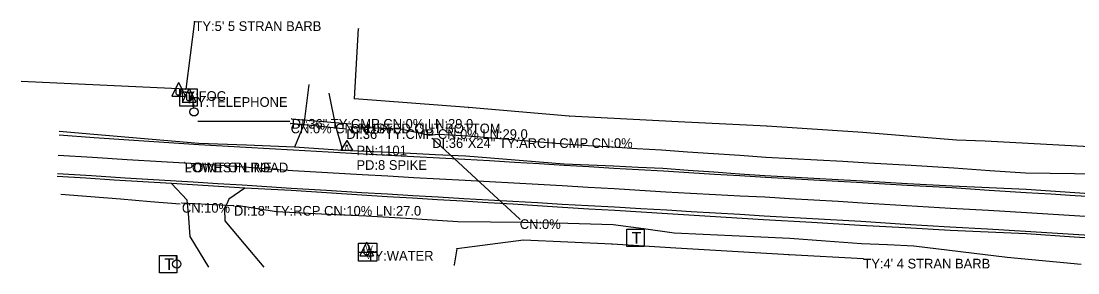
# Model space of a CAD drawing. Extents: x 592653 to 596268, y 1744647 to 1746025.
# Drawn here: x 592653 to 593199, y 1745895 to 1746025 of the extents above; entities that cross this region are included whole.
import ezdxf

# ---------------------------------------------------------------- set-up
doc = ezdxf.new("R2010")
doc.units = 0
for name, color, linetype in [('S_CROSS_DRAIN', 7, 'Continuous'), ('S_CROSS_DRAIN_ANNOT', 7, 'Continuous'), ('S_DITCHLINE', 7, 'Continuous'), ('S_DRG_PT_SYM', 7, 'Continuous'), ('S_DRIVEWAY', 7, 'Continuous'), ('S_EDGE_PAVEMENT', 7, 'Continuous'), ('S_ELECTRIC_UTILITIES_ANNOT', 7, 'Continuous'), ('S_FENCE', 7, 'Continuous'), ('S_FENCE_ANNOT', 7, 'Continuous'), ('S_MSC_PT_SYM', 7, 'Continuous'), ('S_PAVEMENT_CROWN', 7, 'Continuous'), ('S_SECONDARY_CTL', 7, 'Continuous'), ('S_SECONDARY_CTL_ANNOT', 7, 'Continuous'), ('S_SHOULDER', 7, 'Continuous'), ('S_SIDE_DRAIN', 7, 'Continuous'), ('S_SIDE_DRAIN_ANNOT', 7, 'Continuous'), ('S_SURVEY_TEXT_ANNOT', 7, 'Continuous'), ('S_TELEPHONE_UTILITIES', 7, 'Continuous'), ('S_UTILITY_POLE', 7, 'Continuous'), ('S_UTILITY_POLE_ANNOT', 7, 'Continuous'), ('S_UTL_PT_SYM', 7, 'Continuous'), ('S_WATER_UTILITIES', 7, 'Continuous')]:
    doc.layers.add(name, color=color, linetype=linetype)

msp = doc.modelspace()

# ---------------------------------------------------------------- linework, layer by layer
at = {"layer": 'S_CROSS_DRAIN'}
msp.add_line((592865.69, 1745964.34), (592910.93, 1745922.49), dxfattribs=at)
at = {"layer": 'S_DITCHLINE'}
for points in [[(592792.08, 1745973.03), (592768.3, 1745973.05), (592744.51, 1745973.07)], [(593210.37, 1745945.77), (593197.7, 1745945.94), (593185.04, 1745946.1), (593172.37, 1745946.27), (593153.81, 1745947.57), (593135.25, 1745948.88), (593113.22, 1745950.21), (593091.19, 1745951.54), (593077.92, 1745952.27), (593064.64, 1745953.01), (593051.37, 1745953.74), (593038.1, 1745954.47), (593024.61, 1745955.39), (593011.12, 1745956.3), (592997.63, 1745957.21), (592984.14, 1745958.12), (592971.51, 1745958.91), (592958.88, 1745959.69), (592946.25, 1745960.47), (592933.62, 1745961.25), (592908.96, 1745963.35), (592884.29, 1745965.44), (592868.82, 1745966.24), (592864.35, 1745965.72), (592849.46, 1745969.01), (592836.26, 1745969.62), (592823.06, 1745970.23)], [(592735.38, 1745930.29), (592719.99, 1745931.55), (592704.59, 1745932.82), (592689.2, 1745934.08), (592673.8, 1745935.34)], [(593201.1, 1745899.09), (593188.35, 1745900.29), (593175.59, 1745901.49), (593162.84, 1745902.69), (593138.7, 1745905.62), (593114.57, 1745908.55), (593101.03, 1745909.22), (593087.5, 1745909.89), (593068.98, 1745911.25), (593050.45, 1745912.61), (593035.52, 1745913.28), (593020.58, 1745913.94), (593005.65, 1745914.61), (592990.72, 1745915.27), (592974.93, 1745917.47), (592959.14, 1745919.68), (592935.83, 1745920.23), (592912.53, 1745920.78), (592895.73, 1745921.02), (592878.94, 1745921.25), (592855.23, 1745922.67), (592831.53, 1745924.08), (592808.39, 1745925.21), (592785.26, 1745926.35), (592764.59, 1745929.59)]]:
    msp.add_lwpolyline(points, dxfattribs=at)
at = {"layer": 'S_DRG_PT_SYM'}
for points in [[(592793.08, 1745974.32), (592793.08, 1745974.37), (592793.08, 1745974.32), (592793.03, 1745974.32), (592793.08, 1745974.32), (592793.08, 1745974.27), (592793.08, 1745974.32), (592793.13, 1745974.32)], [(592792.53, 1745971.92), (592792.53, 1745971.97), (592792.53, 1745971.92), (592792.48, 1745971.92), (592792.53, 1745971.92), (592792.53, 1745971.87), (592792.53, 1745971.92), (592792.58, 1745971.92)], [(592821.26, 1745969.02), (592821.26, 1745969.07), (592821.26, 1745969.02), (592821.21, 1745969.02), (592821.26, 1745969.02), (592821.26, 1745968.97), (592821.26, 1745969.02), (592821.31, 1745969.02)], [(592823.37, 1745971.73), (592823.37, 1745971.78), (592823.37, 1745971.73), (592823.32, 1745971.73), (592823.37, 1745971.73), (592823.37, 1745971.68), (592823.37, 1745971.73), (592823.42, 1745971.73)], [(592865.69, 1745964.34), (592865.69, 1745964.39), (592865.69, 1745964.34), (592865.64, 1745964.34), (592865.69, 1745964.34), (592865.69, 1745964.29), (592865.69, 1745964.34), (592865.74, 1745964.34)], [(592736.3, 1745930.89), (592736.3, 1745930.94), (592736.3, 1745930.89), (592736.25, 1745930.89), (592736.3, 1745930.89), (592736.3, 1745930.84), (592736.3, 1745930.89), (592736.35, 1745930.89)], [(592763.2, 1745929.37), (592763.2, 1745929.42), (592763.2, 1745929.37), (592763.15, 1745929.37), (592763.2, 1745929.37), (592763.2, 1745929.32), (592763.2, 1745929.37), (592763.25, 1745929.37)], [(592910.93, 1745922.49), (592910.93, 1745922.54), (592910.93, 1745922.49), (592910.88, 1745922.49), (592910.93, 1745922.49), (592910.93, 1745922.44), (592910.93, 1745922.49), (592910.98, 1745922.49)]]:
    msp.add_lwpolyline(points, dxfattribs=at)
at = {"layer": 'S_DRIVEWAY'}
for points in [[(592801.88, 1745992.08), (592799.24, 1745971.38), (592794.43, 1745959.79)], [(592819.54, 1745958.03), (592815.89, 1745970.58), (592812.43, 1745987.67)], [(592750.3, 1745897.83), (592740.6, 1745913.57), (592739.66, 1745925.53), (592739.05, 1745932.35), (592730.87, 1745940.97)], [(592768.88, 1745938.55), (592760.53, 1745932.96), (592758.35, 1745927.78), (592758.42, 1745921.74), (592768.54, 1745909.73), (592778.65, 1745897.71)]]:
    msp.add_lwpolyline(points, dxfattribs=at)
at = {"layer": 'S_EDGE_PAVEMENT'}
for points in [[(593210.51, 1745933.97), (593197.92, 1745934.69), (593185.33, 1745935.41), (593172.74, 1745936.14), (593153.5, 1745937.4), (593134.26, 1745938.67), (593111.16, 1745940.01), (593088.05, 1745941.35), (593075.52, 1745942.04), (593062.99, 1745942.73), (593050.46, 1745943.42), (593037.93, 1745944.11), (593024.74, 1745944.91), (593011.55, 1745945.71), (592998.37, 1745946.51), (592985.18, 1745947.31), (592972.35, 1745948.06), (592959.52, 1745948.81), (592946.68, 1745949.56), (592933.85, 1745950.31), (592921.01, 1745951.08), (592908.17, 1745951.85), (592895.33, 1745952.62), (592882.49, 1745953.38), (592869.38, 1745954.07), (592856.26, 1745954.75), (592843.15, 1745955.44), (592830.03, 1745956.12), (592811.89, 1745957.18), (592793.76, 1745958.24), (592769.41, 1745959.59), (592745.05, 1745960.93), (592727, 1745962.17), (592708.94, 1745963.41), (592690.89, 1745964.65), (592672.83, 1745965.89)], [(593221.91, 1745913.07), (593197.1, 1745914.61), (593172.28, 1745916.15), (593152.75, 1745917.3), (593133.21, 1745918.45), (593110.17, 1745919.85), (593087.13, 1745921.26), (593062.21, 1745922.72), (593037.29, 1745924.18), (593024.71, 1745924.93), (593012.14, 1745925.67), (592999.56, 1745926.41), (592986.99, 1745927.15), (592973.44, 1745927.92), (592959.89, 1745928.68), (592946.34, 1745929.45), (592932.79, 1745930.21), (592920.1, 1745930.92), (592907.41, 1745931.63), (592894.71, 1745932.34), (592882.02, 1745933.05), (592868.84, 1745933.84), (592855.67, 1745934.64), (592842.49, 1745935.44), (592829.31, 1745936.24), (592811.08, 1745937.35), (592792.86, 1745938.46), (592780.17, 1745939.27), (592767.48, 1745940.08), (592754.79, 1745940.89), (592742.1, 1745941.7), (592724.58, 1745942.76), (592707.05, 1745943.81), (592689.53, 1745944.87), (592672.01, 1745945.92)]]:
    msp.add_lwpolyline(points, dxfattribs=at)
at = {"layer": 'S_FENCE'}
for p, q in [((592742.82, 1746024.79), (592738.26, 1745989.68)), ((592825.51, 1745984.66), (592827.58, 1746020.99)), ((592738.26, 1745989.68), (592653.26, 1745993.68)), ((592884.37, 1745980.23), (592825.51, 1745984.66)), ((592936.51, 1745975.85), (592884.37, 1745980.23)), ((592992.8, 1745972.9), (592936.51, 1745975.85)), ((593038.69, 1745970.68), (592992.8, 1745972.9)), ((593088.26, 1745967.33), (593038.69, 1745970.68)), ((593136.69, 1745963.35), (593088.26, 1745967.33)), ((593151.46, 1745962.87), (593136.69, 1745963.35)), ((593223.26, 1745958.93), (593151.46, 1745962.87)), ((592878.42, 1745907.3), (592877.08, 1745898.91)), ((592912.83, 1745911.77), (592878.42, 1745907.3)), ((592958.65, 1745909.7), (592912.83, 1745911.77)), ((592991.58, 1745907.54), (592958.65, 1745909.7)), ((593050.1, 1745904.18), (592991.58, 1745907.54)), ((593088.53, 1745902.08), (593050.1, 1745904.18))]:
    msp.add_line(p, q, dxfattribs=at)
at = {"layer": 'S_MSC_PT_SYM'}
for points in [[(592742.82, 1746024.79), (592742.82, 1746024.84), (592742.82, 1746024.79), (592742.77, 1746024.79), (592742.82, 1746024.79), (592742.82, 1746024.74), (592742.82, 1746024.79), (592742.87, 1746024.79)], [(592827.58, 1746020.99), (592827.58, 1746021.04), (592827.58, 1746020.99), (592827.53, 1746020.99), (592827.58, 1746020.99), (592827.58, 1746020.94), (592827.58, 1746020.99), (592827.63, 1746020.99)], [(592653.26, 1745993.68), (592653.26, 1745993.73), (592653.26, 1745993.68), (592653.21, 1745993.68), (592653.26, 1745993.68), (592653.26, 1745993.63), (592653.26, 1745993.68), (592653.31, 1745993.68)], [(592738.26, 1745989.68), (592738.26, 1745989.73), (592738.26, 1745989.68), (592738.21, 1745989.68), (592738.26, 1745989.68), (592738.26, 1745989.63), (592738.26, 1745989.68), (592738.31, 1745989.68)], [(592825.51, 1745984.66), (592825.51, 1745984.71), (592825.51, 1745984.66), (592825.46, 1745984.66), (592825.51, 1745984.66), (592825.51, 1745984.61), (592825.51, 1745984.66), (592825.56, 1745984.66)], [(592884.37, 1745980.23), (592884.37, 1745980.28), (592884.37, 1745980.23), (592884.32, 1745980.23), (592884.37, 1745980.23), (592884.37, 1745980.18), (592884.37, 1745980.23), (592884.42, 1745980.23)], [(592936.51, 1745975.85), (592936.51, 1745975.9), (592936.51, 1745975.85), (592936.46, 1745975.85), (592936.51, 1745975.85), (592936.51, 1745975.8), (592936.51, 1745975.85), (592936.56, 1745975.85)], [(592992.8, 1745972.9), (592992.8, 1745972.95), (592992.8, 1745972.9), (592992.75, 1745972.9), (592992.8, 1745972.9), (592992.8, 1745972.85), (592992.8, 1745972.9), (592992.85, 1745972.9)], [(593038.69, 1745970.68), (593038.69, 1745970.73), (593038.69, 1745970.68), (593038.64, 1745970.68), (593038.69, 1745970.68), (593038.69, 1745970.63), (593038.69, 1745970.68), (593038.74, 1745970.68)], [(593088.26, 1745967.33), (593088.26, 1745967.38), (593088.26, 1745967.33), (593088.21, 1745967.33), (593088.26, 1745967.33), (593088.26, 1745967.28), (593088.26, 1745967.33), (593088.31, 1745967.33)], [(593136.69, 1745963.35), (593136.69, 1745963.4), (593136.69, 1745963.35), (593136.64, 1745963.35), (593136.69, 1745963.35), (593136.69, 1745963.3), (593136.69, 1745963.35), (593136.74, 1745963.35)], [(593151.46, 1745962.87), (593151.46, 1745962.92), (593151.46, 1745962.87), (593151.41, 1745962.87), (593151.46, 1745962.87), (593151.46, 1745962.82), (593151.46, 1745962.87), (593151.51, 1745962.87)], [(592737.76, 1745951.77), (592737.76, 1745951.82), (592737.76, 1745951.77), (592737.71, 1745951.77), (592737.76, 1745951.77), (592737.76, 1745951.72), (592737.76, 1745951.77), (592737.81, 1745951.77)], [(592878.42, 1745907.3), (592878.42, 1745907.35), (592878.42, 1745907.3), (592878.37, 1745907.3), (592878.42, 1745907.3), (592878.42, 1745907.25), (592878.42, 1745907.3), (592878.47, 1745907.3)], [(592912.83, 1745911.77), (592912.83, 1745911.82), (592912.83, 1745911.77), (592912.78, 1745911.77), (592912.83, 1745911.77), (592912.83, 1745911.72), (592912.83, 1745911.77), (592912.88, 1745911.77)], [(592958.65, 1745909.7), (592958.65, 1745909.75), (592958.65, 1745909.7), (592958.6, 1745909.7), (592958.65, 1745909.7), (592958.65, 1745909.65), (592958.65, 1745909.7), (592958.7, 1745909.7)], [(592991.58, 1745907.54), (592991.58, 1745907.59), (592991.58, 1745907.54), (592991.53, 1745907.54), (592991.58, 1745907.54), (592991.58, 1745907.49), (592991.58, 1745907.54), (592991.63, 1745907.54)], [(593050.1, 1745904.18), (593050.1, 1745904.23), (593050.1, 1745904.18), (593050.05, 1745904.18), (593050.1, 1745904.18), (593050.1, 1745904.13), (593050.1, 1745904.18), (593050.15, 1745904.18)], [(593088.53, 1745902.08), (593088.53, 1745902.13), (593088.53, 1745902.08), (593088.48, 1745902.08), (593088.53, 1745902.08), (593088.53, 1745902.03), (593088.53, 1745902.08), (593088.58, 1745902.08)], [(592877.08, 1745898.91), (592877.08, 1745898.96), (592877.08, 1745898.91), (592877.03, 1745898.91), (592877.08, 1745898.91), (592877.08, 1745898.86), (592877.08, 1745898.91), (592877.13, 1745898.91)]]:
    msp.add_lwpolyline(points, dxfattribs=at)
at = {"layer": 'S_PAVEMENT_CROWN'}
msp.add_lwpolyline([(593222.38, 1745922.77), (593197.56, 1745924.28), (593172.75, 1745925.79), (593153.11, 1745926.96), (593133.47, 1745928.14), (593110.8, 1745929.5), (593088.13, 1745930.86), (593075.51, 1745931.61), (593062.89, 1745932.35), (593050.27, 1745933.09), (593037.65, 1745933.84), (593024.84, 1745934.51), (593012.04, 1745935.18), (592999.23, 1745935.85), (592986.43, 1745936.52), (592973.04, 1745937.33), (592959.66, 1745938.15), (592946.28, 1745938.96), (592932.9, 1745939.77), (592920.37, 1745940.48), (592907.85, 1745941.18), (592895.32, 1745941.88), (592882.79, 1745942.59), (592869.47, 1745943.29), (592856.14, 1745943.99), (592842.81, 1745944.69), (592829.48, 1745945.4), (592811.58, 1745946.46), (592793.68, 1745947.53), (592781.17, 1745948.45), (592768.66, 1745949.37), (592756.15, 1745950.29), (592743.64, 1745951.21), (592725.8, 1745952.25), (592707.96, 1745953.29), (592690.12, 1745954.33), (592672.28, 1745955.37)], dxfattribs=at)
at = {"layer": 'S_SECONDARY_CTL'}
for p, q in [((592821.53, 1745963.14), (592818.52, 1745958.18)), ((592821.53, 1745963.14), (592824.48, 1745958.18)), ((592818.52, 1745958.18), (592824.48, 1745958.18))]:
    msp.add_line(p, q, dxfattribs=at)
for radius in [0.311, 0.183, 0.103]:
    msp.add_circle((592821.53, 1745960.53), radius, dxfattribs=at)
at = {"layer": 'S_SHOULDER'}
for points in [[(593210.42, 1745935.35), (593197.82, 1745936.2), (593185.22, 1745937.05), (593172.62, 1745937.91), (593153.47, 1745938.76), (593134.33, 1745939.6), (593111.26, 1745940.87), (593088.19, 1745942.13), (593075.55, 1745942.82), (593062.92, 1745943.51), (593050.29, 1745944.2), (593037.66, 1745944.88), (593024.44, 1745945.84), (593011.23, 1745946.79), (592998.02, 1745947.74), (592984.81, 1745948.7), (592972.08, 1745949.27), (592959.34, 1745949.85), (592946.61, 1745950.43), (592933.87, 1745951), (592921.18, 1745952.03), (592908.49, 1745953.06), (592895.79, 1745954.09), (592883.1, 1745955.11), (592867.21, 1745955.84), (592851.32, 1745956.57), (592835.43, 1745957.3), (592819.54, 1745958.03), (592806.99, 1745958.91), (592794.43, 1745959.79), (592769.71, 1745960.73), (592744.99, 1745961.67), (592726.94, 1745963.23), (592708.89, 1745964.79), (592690.84, 1745966.35), (592672.79, 1745967.91)], [(593221.99, 1745911.68), (593197.4, 1745913.32), (593172.8, 1745914.96), (593153.07, 1745915.87), (593133.34, 1745916.77), (593110.07, 1745918.06), (593086.8, 1745919.34), (593061.88, 1745920.81), (593036.96, 1745922.28), (593012.1, 1745923.8), (592987.24, 1745925.33), (592973.68, 1745926.15), (592960.12, 1745926.97), (592946.57, 1745927.79), (592933.01, 1745928.61), (592920.14, 1745929.42), (592907.27, 1745930.23), (592894.4, 1745931.03), (592881.54, 1745931.84), (592868.47, 1745932.6), (592855.41, 1745933.36), (592842.35, 1745934.12), (592829.29, 1745934.89), (592811.06, 1745936.09), (592792.83, 1745937.29), (592768.88, 1745938.55), (592749.88, 1745939.76), (592730.87, 1745940.97), (592716.12, 1745941.87), (592701.37, 1745942.78), (592686.61, 1745943.68), (592671.86, 1745944.59)]]:
    msp.add_lwpolyline(points, dxfattribs=at)
at = {"layer": 'S_SIDE_DRAIN'}
for p, q in [((592793.08, 1745974.32), (592823.37, 1745971.73)), ((592821.26, 1745969.02), (592792.53, 1745971.92)), ((592763.2, 1745929.37), (592736.3, 1745930.89))]:
    msp.add_line(p, q, dxfattribs=at)
at = {"layer": 'S_TELEPHONE_UTILITIES'}
for points in [[(592735.22, 1745980.89), (592735.22, 1745989.89), (592744.22, 1745989.89), (592744.22, 1745980.89)], [(592966.23, 1745908.42), (592966.23, 1745917.42), (592975.23, 1745917.42), (592975.23, 1745908.42)], [(592724.73, 1745894.81), (592724.73, 1745903.81), (592733.73, 1745903.81), (592733.73, 1745894.81)]]:
    msp.add_lwpolyline(points, close=True, dxfattribs=at)
at = {"layer": 'S_UTILITY_POLE'}
for p, q in [((592734.59, 1745993.21), (592731.07, 1745986.12)), ((592733.39, 1745987.36), (592733.39, 1745989.8)), ((592734.59, 1745993.21), (592738.08, 1745986.12)), ((592735.76, 1745989.8), (592735.76, 1745987.36)), ((592740.02, 1745990.12), (592736.49, 1745983.03)), ((592740.02, 1745990.12), (592743.5, 1745983.03)), ((592731.07, 1745986.12), (592738.08, 1745986.12)), ((592734.01, 1745986.7), (592733.39, 1745987.36)), ((592735.21, 1745986.7), (592734.01, 1745986.7)), ((592735.76, 1745987.36), (592735.21, 1745986.7)), ((592738.82, 1745984.27), (592738.82, 1745986.71)), ((592739.44, 1745983.61), (592738.82, 1745984.27)), ((592740.64, 1745983.61), (592739.44, 1745983.61)), ((592741.18, 1745984.27), (592740.64, 1745983.61)), ((592741.18, 1745986.71), (592741.18, 1745984.27)), ((592736.49, 1745983.03), (592743.5, 1745983.03)), ((592742.44, 1745980.13), (592742.44, 1745982.24)), ((592831.8, 1745910.67), (592828.27, 1745903.58)), ((592830.59, 1745904.82), (592830.59, 1745907.26)), ((592831.8, 1745910.67), (592835.28, 1745903.58)), ((592832.96, 1745907.26), (592832.96, 1745904.82)), ((592733.53, 1745901.5), (592733.53, 1745903.61)), ((592828.27, 1745903.58), (592835.28, 1745903.58)), ((592831.21, 1745904.16), (592830.59, 1745904.82)), ((592832.42, 1745904.16), (592831.21, 1745904.16)), ((592832.96, 1745904.82), (592832.42, 1745904.16))]:
    msp.add_line(p, q, dxfattribs=at)
for centre in [(592742.57, 1745977.99), (592733.65, 1745899.36)]:
    msp.add_circle(centre, 2.13, dxfattribs=at)
at = {"layer": 'S_UTL_PT_SYM'}
msp.add_lwpolyline([(592737.76, 1745951.77), (592737.76, 1745951.82), (592737.76, 1745951.77), (592737.71, 1745951.77), (592737.76, 1745951.77), (592737.76, 1745951.72), (592737.76, 1745951.77), (592737.81, 1745951.77)], dxfattribs=at)
at = {"layer": 'S_WATER_UTILITIES'}
for p, q in [((592827.62, 1745910.22), (592837.04, 1745910.22)), ((592827.62, 1745900.8), (592827.62, 1745910.22)), ((592837.04, 1745910.22), (592837.04, 1745900.8)), ((592827.62, 1745905.53), (592837.04, 1745905.53)), ((592837.04, 1745900.8), (592827.62, 1745900.8))]:
    msp.add_line(p, q, dxfattribs=at)

# ---------------------------------------------------------------- texts
at = {"layer": 'S_CROSS_DRAIN_ANNOT'}
for s, p in [('DI:36"X24" TY:ARCH CMP CN:0%', (592865.69, 1745959.34)), ('CN:0%', (592910.93, 1745917.49))]:
    msp.add_text(s, height=5, dxfattribs=at).set_placement(p)
at = {"layer": 'S_ELECTRIC_UTILITIES_ANNOT'}
msp.add_text('LOWEST LINE', height=5, dxfattribs=at).set_placement((592737.76, 1745946.77))
at = {"layer": 'S_FENCE_ANNOT'}
for s, p in [("TY:5' 5 STRAN BARB", (592742.82, 1746019.79)), ("TY:4' 4 STRAN BARB", (593088.53, 1745897.08))]:
    msp.add_text(s, height=5, dxfattribs=at).set_placement(p)
at = {"layer": 'S_SECONDARY_CTL'}
msp.add_text('TV', height=1.5, rotation=360, dxfattribs=at).set_placement((592820.32, 1745958.52))
at = {"layer": 'S_SECONDARY_CTL_ANNOT'}
for s, p in [('PN:1101', (592826.53, 1745955.53)), ('PD:8 SPIKE', (592826.53, 1745948.03))]:
    msp.add_text(s, height=5, dxfattribs=at).set_placement(p)
at = {"layer": 'S_SIDE_DRAIN_ANNOT'}
for s, p in [('DI:36" TY:CMP CN:0% LN:29.0', (592793.08, 1745969.32)), ('CN:0% CN:RUSTED OUT BOTTOM', (592792.53, 1745966.92)), ('DI:36" TY:CMP CN:0% LN:29.0', (592821.26, 1745964.02)), ('CN:0%', (592823.37, 1745966.73)), ('CN:10%', (592736.3, 1745925.89)), ('DI:18" TY:RCP CN:10% LN:27.0', (592763.2, 1745924.37))]:
    msp.add_text(s, height=5, dxfattribs=at).set_placement(p)
at = {"layer": 'S_SURVEY_TEXT_ANNOT'}
msp.add_text('POINT ON ROAD', height=5, dxfattribs=at).set_placement((592737.76, 1745946.77))
at = {"layer": 'S_TELEPHONE_UTILITIES'}
for p in [(592737.79, 1745982.39), (592968.79, 1745909.92), (592727.3, 1745896.31)]:
    msp.add_text('T', height=6, rotation=360, dxfattribs=at).set_placement(p)
at = {"layer": 'S_UTILITY_POLE_ANNOT'}
for s, p in [('TY:FOC', (592734.59, 1745983.68)), ('TY:TELEPHONE', (592740.02, 1745980.59)), ('TY:WATER', (592831.8, 1745901.14))]:
    msp.add_text(s, height=5, dxfattribs=at).set_placement(p)
at = {"layer": 'S_WATER_UTILITIES'}
for s, p in [('W', (592831.17, 1745906.06)), ('V', (592831.41, 1745902))]:
    msp.add_text(s, height=3, rotation=360, dxfattribs=at).set_placement(p)

doc.saveas('drawing.dxf')
